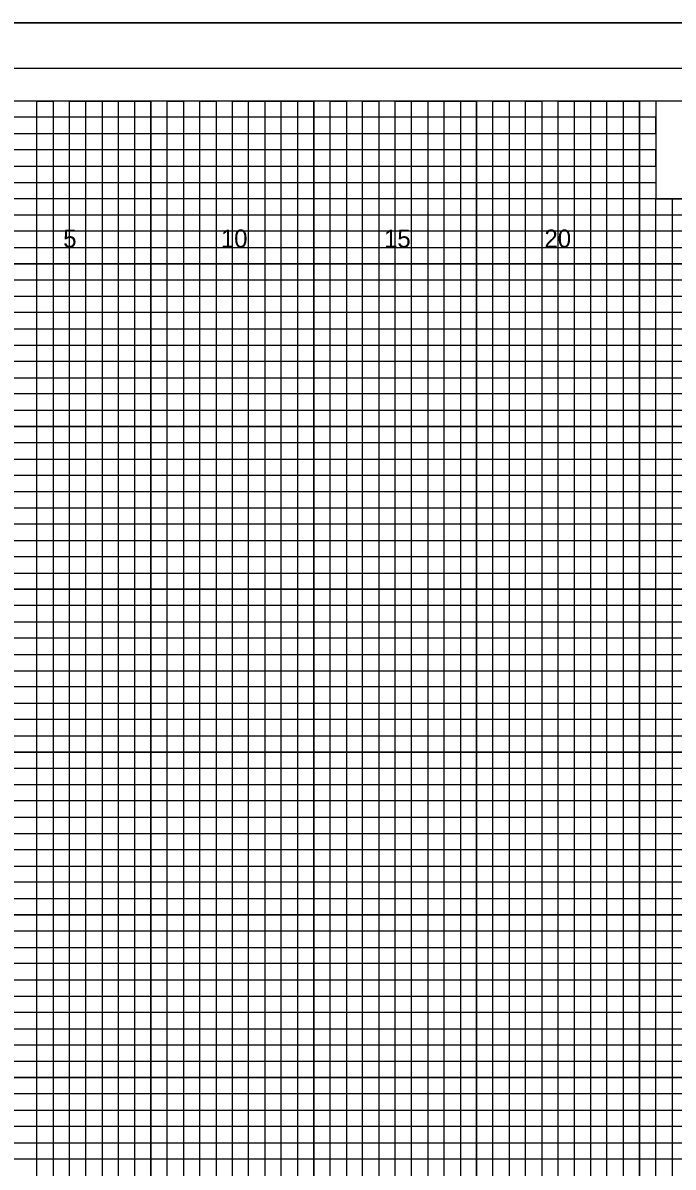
# Model space of a CAD drawing. Extents: x -4 to 103, y -2 to 138.
# Drawn here: x 54.82 to 74.78, y 32.25 to 67.4 of the extents above; entities that cross this region are included whole.
import ezdxf

# ---------------------------------------------------------------- set-up
doc = ezdxf.new("R2010")
doc.units = 0
for name, color, linetype in [('Old_Level_10', 7, 'Continuous'), ('Old_Level_3', 7, 'Continuous'), ('Old_Level_4', 7, 'Continuous'), ('Old_Level_5', 7, 'Continuous'), ('Old_Level_8', 7, 'Continuous'), ('Prop XS Elevation Labels', 7, 'Continuous'), ('Prop XS Finish Grade', 7, 'Continuous'), ('Prop XS Finish Grade Pavement', 7, 'Continuous')]:
    doc.layers.add(name, color=color, linetype=linetype)

msp = doc.modelspace()

# ---------------------------------------------------------------- linework, layer by layer
at = {"layer": 'Old_Level_10'}
for p, q in [((56.25, 0), (56.25, 65)), ((58.75, 0), (58.75, 65)), ((61.25, 0), (61.25, 65)), ((63.75, 0), (63.75, 65)), ((66.25, 0), (66.25, 65)), ((68.75, 0), (68.75, 65)), ((71.25, 0), (71.25, 65)), ((73.75, 0), (73.75, 65)), ((0, 62.5), (74.25, 62.5)), ((0, 60), (102.5, 60)), ((0, 57.5), (102.5, 57.5)), ((0, 55), (102.5, 55)), ((0, 52.5), (102.5, 52.5)), ((0, 50), (102.5, 50)), ((0, 47.5), (102.5, 47.5)), ((0, 45), (102.5, 45)), ((0, 42.5), (102.5, 42.5)), ((0, 40), (102.5, 40)), ((0, 37.5), (102.5, 37.5)), ((0, 35), (102.5, 35)), ((0, 32.5), (102.5, 32.5))]:
    msp.add_line(p, q, dxfattribs=at)
at = {"layer": 'Old_Level_3'}
msp.add_line((-3.5, 67.4), (103.4, 67.4), dxfattribs=at)
at = {"layer": 'Old_Level_4'}
msp.add_lwpolyline([(103, 66), (-2.8, 66), (-2.8, -1), (103, -1)], close=True, dxfattribs=at)
at = {"layer": 'Old_Level_5'}
msp.add_lwpolyline([(103.4, 67.4), (-3.5, 67.4), (-3.5, -2.425), (103.4, -2.425)], close=True, dxfattribs=at)
at = {"layer": 'Old_Level_8'}
for points in [[(56.25, 0), (56.25, 65), (58.75, 65), (58.75, 0)], [(61.25, 0), (61.25, 65), (63.75, 65), (63.75, 0)], [(66.25, 0), (66.25, 65), (68.75, 65), (68.75, 0)], [(71.25, 0), (71.25, 65), (73.75, 65), (73.75, 0)], [(0, 62.5), (74.25, 62.5)], [(0, 57.5), (102.5, 57.5), (102.5, 60), (0, 60)], [(0, 52.5), (102.5, 52.5), (102.5, 55), (0, 55)], [(0, 47.5), (102.5, 47.5), (102.5, 50), (0, 50)], [(0, 42.5), (102.5, 42.5), (102.5, 45), (0, 45)], [(0, 37.5), (102.5, 37.5), (102.5, 40), (0, 40)], [(0, 32.5), (102.5, 32.5), (102.5, 35), (0, 35)]]:
    msp.add_lwpolyline(points, dxfattribs=at)
at = {"layer": 'Prop XS Elevation Labels'}
for points in [[(102.5, 65), (0, 65), (0, 0), (102.5, 0)], [(83.75, 65), (74.25, 65), (74.25, 62), (83.75, 62)]]:
    msp.add_lwpolyline(points, close=True, dxfattribs=at)
at = {"layer": 'Prop XS Finish Grade'}
for points in [[(55.25, 0), (55.25, 65), (55.75, 65), (55.75, 0)], [(56.75, 0), (56.75, 65), (57.25, 65), (57.25, 0)], [(57.75, 0), (57.75, 65), (58.25, 65), (58.25, 0)], [(59.25, 0), (59.25, 65), (59.75, 65), (59.75, 0)], [(60.25, 0), (60.25, 65), (60.75, 65), (60.75, 0)], [(61.75, 0), (61.75, 65), (62.25, 65), (62.25, 0)], [(62.75, 0), (62.75, 65), (63.25, 65), (63.25, 0)], [(64.25, 0), (64.25, 65), (64.75, 65), (64.75, 0)], [(65.25, 0), (65.25, 65), (65.75, 65), (65.75, 0)], [(66.75, 0), (66.75, 65), (67.25, 65), (67.25, 0)], [(67.75, 0), (67.75, 65), (68.25, 65), (68.25, 0)], [(69.25, 0), (69.25, 65)], [(69.25, 65), (69.75, 65), (69.75, 0)], [(70.25, 0), (70.25, 65), (70.75, 65), (70.75, 0)], [(71.75, 0), (71.75, 65), (72.25, 65), (72.25, 0)], [(72.75, 0), (72.75, 65), (73.25, 65), (73.25, 0)], [(0, 62), (0, 63), (74.25, 63), (74.25, 63.5), (0, 63.5), (0, 64), (74.25, 64), (74.25, 64.5), (0, 64.5)], [(0, 61.5), (102.5, 61.5), (102.5, 62), (0, 62)], [(74.25, 0), (74.25, 62), (74.75, 62), (74.75, 0)], [(0, 60.5), (102.5, 60.5), (102.5, 61), (0, 61)], [(0, 59), (102.5, 59), (102.5, 59.5), (0, 59.5)], [(0, 58), (102.5, 58), (102.5, 58.5), (0, 58.5)], [(0, 56.5), (102.5, 56.5), (102.5, 57), (0, 57)], [(0, 55.5), (102.5, 55.5), (102.5, 56), (0, 56)], [(0, 54), (102.5, 54), (102.5, 54.5), (0, 54.5)], [(0, 53), (102.5, 53), (102.5, 53.5), (0, 53.5)], [(0, 51.5), (102.5, 51.5), (102.5, 52), (0, 52)], [(0, 50.5), (102.5, 50.5), (102.5, 51), (0, 51)], [(0, 49), (102.5, 49), (102.5, 49.5), (0, 49.5)], [(0, 48), (102.5, 48), (102.5, 48.5), (0, 48.5)], [(0, 46.5), (102.5, 46.5), (102.5, 47), (0, 47)], [(0, 45.5), (102.5, 45.5), (102.5, 46), (0, 46)], [(0, 44), (102.5, 44), (102.5, 44.5), (0, 44.5)], [(0, 43), (102.5, 43), (102.5, 43.5), (0, 43.5)], [(0, 41.5), (102.5, 41.5), (102.5, 42), (0, 42)], [(0, 40.5), (102.5, 40.5), (102.5, 41), (0, 41)], [(0, 39), (102.5, 39), (102.5, 39.5), (0, 39.5)], [(0, 38), (102.5, 38), (102.5, 38.5), (0, 38.5)], [(0, 36.5), (102.5, 36.5), (102.5, 37), (0, 37)], [(0, 35.5), (102.5, 35.5), (102.5, 36), (0, 36)], [(0, 34), (102.5, 34), (102.5, 34.5), (0, 34.5)], [(0, 33), (102.5, 33), (102.5, 33.5), (0, 33.5)]]:
    msp.add_lwpolyline(points, dxfattribs=at)

# ---------------------------------------------------------------- texts
at = {"layer": 'Prop XS Finish Grade Pavement'}
for s, p in [('5', (56.057, 60.5)), ('10', (60.897, 60.5)), ('15', (65.906, 60.5)), ('20', (70.831, 60.5))]:
    msp.add_text(s, height=0.55, dxfattribs=at).set_placement(p)

doc.saveas('drawing.dxf')
